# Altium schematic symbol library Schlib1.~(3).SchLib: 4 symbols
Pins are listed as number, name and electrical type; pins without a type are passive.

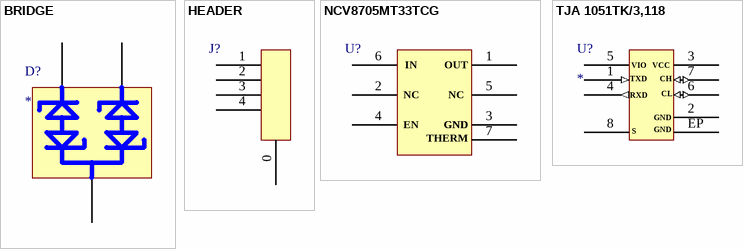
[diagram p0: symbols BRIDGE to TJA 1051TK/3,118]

## BRIDGE
designator D?
pins: 1, 2, 3

## HEADER
designator J?  (value not drawn)
pins: 0, 1, 2, 3, 4

## NCV8705MT33TCG
designator U?  (value not drawn)
pins: 1, 2, 3, 4, 5, 6, 7

## TJA 1051TK/3,118
designator U?
pins: 1 (in), 2, 3, 4 (out), 5, 6 (io), 7 (io), 8, EP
